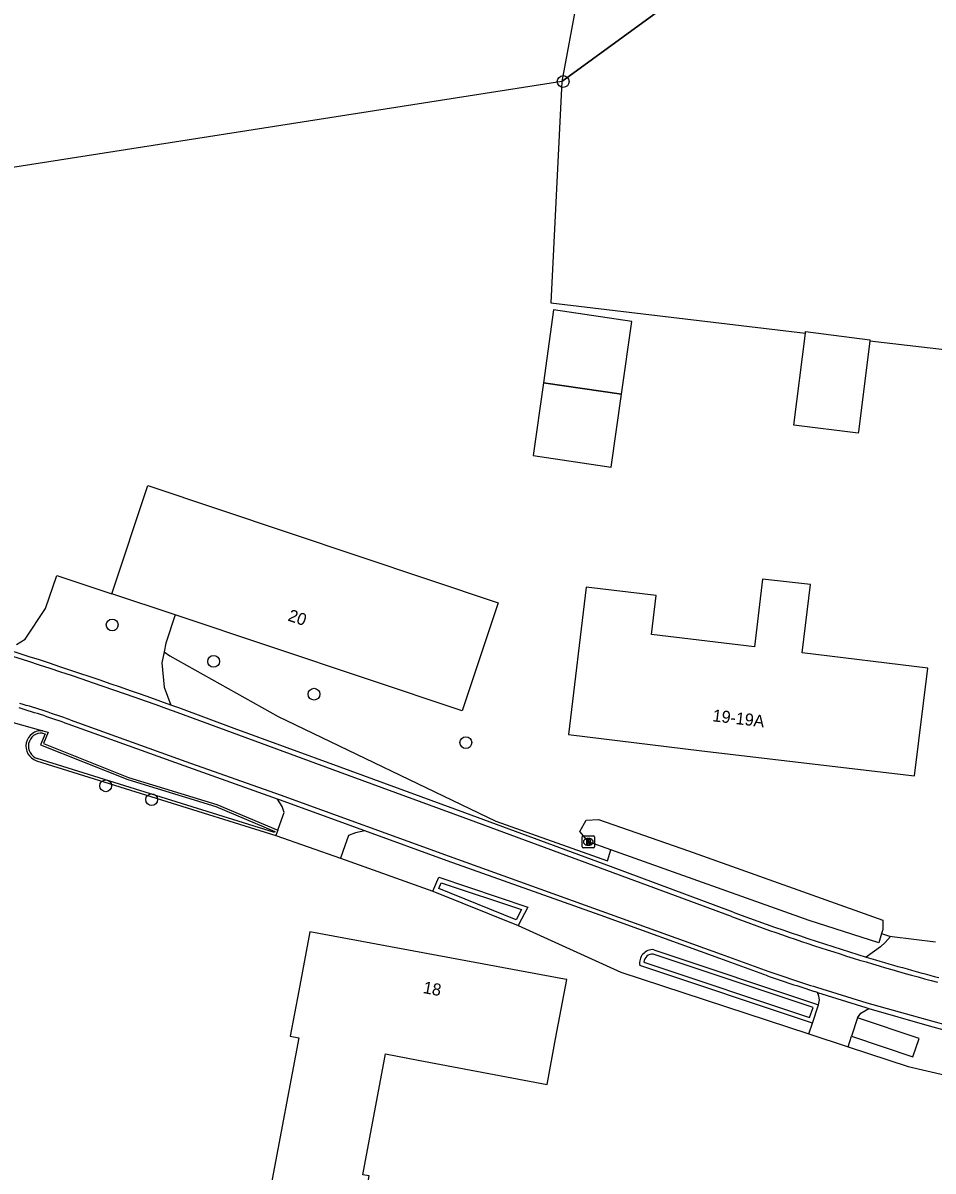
# Model space of a CAD drawing. Extents: x 162515 to 163909, y 388494 to 389773.
# Drawn here: x 162571.4 to 162646.9, y 389047 to 389142.1 of the extents above; entities that cross this region are included whole.
import ezdxf

# ---------------------------------------------------------------- set-up
doc = ezdxf.new("R2010")
doc.units = 0
for name, color, linetype in [('IMGEO_Berm_groen', 7, 'Continuous'), ('IMGEO_Boom', 7, 'Continuous'), ('IMGEO_Erf', 7, 'Continuous'), ('IMGEO_Grasland_agrarisch', 7, 'Continuous'), ('IMGEO_Grasland_overig', 7, 'Continuous'), ('IMGEO_Groenvoorziening', 7, 'Continuous'), ('IMGEO_Hek', 7, 'Continuous'), ('IMGEO_Loofbos', 7, 'Continuous'), ('IMGEO_Pand', 7, 'Continuous'), ('IMGEO_Pand_nummerreeks', 7, 'Continuous'), ('IMGEO_Pand_overbouw', 7, 'Continuous'), ('IMGEO_Rijbaan_lokaal_gesloten', 7, 'Continuous'), ('IMGEO_Rijbaan_lokaal_halfverhard', 7, 'Continuous'), ('IMGEO_Rijbaan_lokaal_open', 7, 'Continuous'), ('IMGEO_Rioolput', 7, 'Continuous'), ('IMGEO_Voetpad_halfverhard', 7, 'Continuous'), ('IMGEO_Voetpad_open', 7, 'Continuous'), ('IMGEO_Waterloop', 7, 'Continuous')]:
    doc.layers.add(name, color=color, linetype=linetype)

msp = doc.modelspace()

# ---------------------------------------------------------------- linework, layer by layer
at = {"layer": 'IMGEO_Berm_groen'}
for points in [[(162597.772, 389072.896), (162605.424, 389070.178)], [(162605.424, 389070.178), (162605.91, 389071.318), (162613.301, 389068.852), (162612.506, 389067.31)], [(162612.506, 389067.31), (162621.016, 389063.464), (162636.603, 389058.338)], [(162623.752, 389065.315), (162637.408, 389060.743)], [(162636.901, 389059.229), (162622.591, 389064.006)]]:
    msp.add_lwpolyline(points, dxfattribs=at)
msp.add_arc((162623.672, 389064.216), 1.102, 85.85497, 191.00304, dxfattribs=at)
at = {"layer": 'IMGEO_Boom'}
for centre in [(162616.233, 389137.29), (162578.829, 389092.237), (162587.236, 389089.214), (162595.566, 389086.496), (162608.163, 389082.483), (162578.292, 389078.903), (162582.101, 389077.76)]:
    msp.add_circle(centre, 0.489, dxfattribs=at)
at = {"layer": 'IMGEO_Erf'}
for points in [[(162572.538, 389080.978), (162592.401, 389074.784)], [(162605.424, 389070.178), (162612.506, 389067.31)]]:
    msp.add_lwpolyline(points, dxfattribs=at)
msp.add_arc((162572.96, 389082.191), 1.284, 84.97508, 250.8354, dxfattribs=at)
at = {"layer": 'IMGEO_Grasland_agrarisch'}
msp.add_lwpolyline([(162616.111, 389137.29), (162556.609, 389127.989)], dxfattribs=at)
at = {"layer": 'IMGEO_Grasland_overig'}
msp.add_lwpolyline([(162633.62, 389150.066), (162631.291, 389155.256), (162618.597, 389150.697), (162616.111, 389137.29)], dxfattribs=at)
at = {"layer": 'IMGEO_Groenvoorziening'}
for points in [[(162583.138, 389090.012), (162583.595, 389089.671), (162592.606, 389084.643), (162610.637, 389075.969), (162619.919, 389072.683), (162620.188, 389073.585)], [(162557.784, 389085.129), (162560.951, 389085.473), (162565.003, 389085.162), (162565.92, 389085.075), (162567.934, 389084.89), (162573.072, 389083.47)], [(162573.072, 389083.47), (162573.519, 389083.346), (162573.142, 389082.396), (162580.177, 389079.602), (162587.495, 389077.364), (162592.559, 389075.234)], [(162642.646, 389066.648), (162643.381, 389066.421)], [(162639.858, 389057.267), (162644.844, 389055.627), (162677.463, 389048.046)]]:
    msp.add_lwpolyline(points, dxfattribs=at)
at = {"layer": 'IMGEO_Hek'}
msp.add_lwpolyline([(162616.111, 389137.29), (162633.62, 389150.066)], dxfattribs=at)
at = {"layer": 'IMGEO_Loofbos'}
for points in [[(162633.62, 389150.066), (162616.111, 389137.29)], [(162616.111, 389137.29), (162615.215, 389118.938), (162636.321, 389116.436)], [(162641.662, 389115.802), (162650.943, 389114.702), (162655.896, 389114.06)]]:
    msp.add_lwpolyline(points, dxfattribs=at)
at = {"layer": 'IMGEO_Pand'}
for points in [[(162621.939, 389117.404), (162615.419, 389118.366), (162614.587, 389112.323), (162621.077, 389111.365), (162621.939, 389117.404)], [(162641.662, 389115.802), (162640.716, 389108.261), (162640.699, 389108.128), (162635.361, 389108.798), (162636.321, 389116.436)], [(162636.321, 389116.436), (162636.336, 389116.556), (162641.673, 389115.886), (162641.662, 389115.802)], [(162578.784, 389094.826), (162581.781, 389103.795), (162610.841, 389094.076), (162607.844, 389085.107), (162584.039, 389093.069)], [(162632.766, 389096.037), (162632.094, 389090.417), (162623.545, 389091.44), (162623.932, 389094.677), (162618.144, 389095.37), (162616.682, 389083.157), (162627.737, 389081.795), (162645.378, 389079.737), (162646.476, 389088.646), (162636.045, 389089.931), (162636.741, 389095.589), (162632.766, 389096.037)], [(162584.039, 389093.069), (162578.784, 389094.826)], [(162604.218, 389056.155), (162614.892, 389054.138), (162615.607, 389057.921), (162616.534, 389062.834), (162616.336, 389062.871), (162595.223, 389066.807), (162594.294, 389061.894), (162593.588, 389058.156), (162594.315, 389058.019), (162592.019, 389045.861), (162592.557, 389045.76), (162591.005, 389037.546), (162598.18, 389036.191), (162600.085, 389046.274), (162600.138, 389046.554), (162599.608, 389046.654), (162601.5, 389056.669), (162604.218, 389056.155)]]:
    msp.add_lwpolyline(points, dxfattribs=at)
at = {"layer": 'IMGEO_Pand_overbouw'}
msp.add_lwpolyline([(162621.077, 389111.365), (162614.587, 389112.323), (162613.755, 389106.274), (162620.212, 389105.312)], close=True, dxfattribs=at)
at = {"layer": 'IMGEO_Rijbaan_lokaal_gesloten'}
for points in [[(162575.34, 389084.366), (162584.931, 389080.923), (162592.748, 389078.167), (162606.773, 389073.076), (162619.448, 389068.517), (162629.327, 389064.949), (162633.3, 389063.513)], [(162630.186, 389068.059), (162619.847, 389071.883), (162607.927, 389076.278), (162597.591, 389080.066), (162588.792, 389083.287), (162584.227, 389084.98)], [(162637.231, 389062.201), (162641.418, 389060.909), (162646.781, 389059.42)]]:
    msp.add_lwpolyline(points, dxfattribs=at)
for centre, radius, start, end in [((162449.728, 388712.327), 396.182, 70.1543, 72.30597), ((162553.555, 389024.708), 63.511, 69.93984, 73.89327), ((162694.778, 389241.263), 184.855, 249.54836, 255.11406), ((162695.7, 389243.931), 190.905, 250.92129, 252.16509), ((162697.827, 389234.609), 182.474, 253.75498, 259.99234)]:
    msp.add_arc(centre, radius, start, end, dxfattribs=at)
at = {"layer": 'IMGEO_Rijbaan_lokaal_halfverhard'}
for points in [[(162630.325, 389068.434), (162620.144, 389072.2), (162608.065, 389076.654), (162597.729, 389080.442), (162588.931, 389083.662), (162584.363, 389085.356), (162583.689, 389085.599)], [(162592.545, 389077.801), (162584.785, 389080.564), (162575.172, 389084.009)], [(162599.769, 389075.181), (162592.692, 389077.749), (162592.545, 389077.801)], [(162633.167, 389063.141), (162629.224, 389064.578), (162619.309, 389068.164), (162606.622, 389072.695), (162599.769, 389075.181)], [(162637.328, 389061.772), (162637.079, 389061.849)], [(162637.328, 389061.772), (162641.34, 389060.522), (162641.596, 389060.449)], [(162641.596, 389060.449), (162646.599, 389059.011)]]:
    msp.add_lwpolyline(points, dxfattribs=at)
for centre, radius, start, end in [((162553.636, 389025.702), 62.157, 69.72791, 73.68109), ((162694.824, 389241.388), 184.589, 249.54808, 253.16879), ((162695.81, 389244.987), 188.32, 253.19886, 255.10164), ((163018.716, 390223.963), 1223.174, 251.626885, 251.819865), ((162705.983, 389271.927), 221.042, 254.41588, 259.58886)]:
    msp.add_arc(centre, radius, start, end, dxfattribs=at)
at = {"layer": 'IMGEO_Rijbaan_lokaal_open'}
for points in [[(162570.879, 389090.626), (162571.596, 389091.063), (162573.303, 389093.589), (162574.241, 389096.331), (162578.784, 389094.826)], [(162584.039, 389093.069), (162583.288, 389090.735), (162583.138, 389090.012)], [(162583.138, 389090.012), (162582.949, 389089.105), (162583.143, 389087.072), (162583.689, 389085.599)]]:
    msp.add_lwpolyline(points, dxfattribs=at)
msp.add_arc((162450.179, 388713.593), 395.238, 70.25732, 72.31315, dxfattribs=at)
at = {"layer": 'IMGEO_Rioolput'}
for p, q in [((162617.818, 389073.829), (162617.818, 389074.681)), ((162617.893, 389074.755), (162618.745, 389074.755)), ((162618.819, 389074.681), (162618.819, 389073.829)), ((162618.745, 389073.755), (162617.893, 389073.755)), ((162618.329, 389073.975), (162618.304, 389073.975)), ((162618.306, 389074.535), (162618.331, 389074.535))]:
    msp.add_line(p, q, dxfattribs=at)
for points in [[(162617.818, 389073.829), (162617.818, 389074.681)], [(162617.893, 389074.755), (162618.745, 389074.755)], [(162618.819, 389074.681), (162618.819, 389073.829)], [(162618.745, 389073.755), (162617.893, 389073.755)], [(162618.407, 389074.453), (162618.155, 389074.455), (162618.155, 389074.055)], [(162618.155, 389074.055), (162618.279, 389074.055), (162618.279, 389074.217), (162618.29, 389074.217)], [(162618.333, 389074.374), (162618.279, 389074.374), (162618.279, 389074.293)], [(162618.279, 389074.293), (162618.331, 389074.293)], [(162618.337, 389074.188), (162618.408, 389074.055), (162618.548, 389074.055), (162618.483, 389074.181)]]:
    msp.add_lwpolyline(points, dxfattribs=at)
for centre, radius, start, end in [((162617.895, 389074.679), 0.0765, 91.55205, 178.44795), ((162617.895, 389074.679), 0.0765, 91.55205, 178.44795), ((162618.743, 389074.679), 0.0765, 1.55205, 88.44795), ((162618.743, 389074.679), 0.0765, 1.55205, 88.44795), ((162617.895, 389073.831), 0.0765, 181.55205, 268.44795), ((162617.895, 389073.831), 0.0765, 181.55205, 268.44795), ((162618.289, 389074.164), 0.0533, 26.02933, 88.69889), ((162618.315, 389074.482), 0.19, 274.7715, 282.96867), ((162618.339, 389074.278), 0.0964, 77.00612, 93.18647), ((162618.353, 389074.335), 0.0378, 276.66336, 79.67722), ((162618.406, 389074.343), 0.109, 350.36119, 89.41601), ((162618.404, 389074.343), 0.112, 277.58423, 350.98172), ((162618.388, 389074.128), 0.108, 29.51342, 73.79051), ((162618.743, 389073.831), 0.0765, 271.55205, 358.44795), ((162618.743, 389073.831), 0.0765, 271.55205, 358.44795)]:
    msp.add_arc(centre, radius, start, end, dxfattribs=at)
for centre, major_axis, ratio, start_param, end_param in [((162618.305, 389074.255), (-0.387, 0.002), 0.722429, 4.712389, 7.853982), ((162618.33, 389074.255), (-0.39, 0.002), 0.717154, 1.570796, 4.712389)]:
    msp.add_ellipse(centre, major_axis=major_axis, ratio=ratio, start_param=start_param, end_param=end_param, dxfattribs=at)
at = {"layer": 'IMGEO_Voetpad_halfverhard'}
for points in [[(162592.559, 389075.234), (162592.998, 389076.477), (162593.077, 389076.701), (162592.93, 389077.198), (162592.545, 389077.801)], [(162592.559, 389075.234), (162592.401, 389074.784)], [(162592.401, 389074.784), (162597.772, 389072.896)], [(162599.769, 389075.181), (162599.005, 389075.013), (162598.439, 389074.769), (162598.136, 389073.919), (162597.772, 389072.896)]]:
    msp.add_lwpolyline(points, dxfattribs=at)
at = {"layer": 'IMGEO_Voetpad_open'}
for points in [[(162643.381, 389066.421), (162642.952, 389065.907), (162642.557, 389065.555), (162641.376, 389064.706)], [(162647.102, 389065.938), (162643.518, 389066.379), (162643.381, 389066.421)], [(162637.408, 389060.743), (162637.478, 389061.162), (162637.435, 389061.466), (162637.328, 389061.772)], [(162636.901, 389059.229), (162637.408, 389060.743)], [(162640.657, 389059.656), (162640.933, 389060.049), (162641.251, 389060.258), (162641.596, 389060.449)], [(162640.657, 389059.656), (162640.151, 389058.145)], [(162636.603, 389058.338), (162636.901, 389059.229)], [(162636.603, 389058.338), (162639.858, 389057.267)], [(162639.858, 389057.267), (162640.151, 389058.145)]]:
    msp.add_lwpolyline(points, dxfattribs=at)
at = {"layer": 'IMGEO_Waterloop'}
for points in [[(162573.045, 389083.274), (162573.256, 389083.215), (162572.887, 389082.286), (162580.112, 389079.417), (162587.428, 389077.179), (162592.313, 389075.125), (162592.279, 389075.028), (162572.607, 389081.162)], [(162620.188, 389073.585), (162618.326, 389074.249), (162617.612, 389075.122), (162618.128, 389076.056), (162619.16, 389076.114), (162626.637, 389073.516), (162642.734, 389067.769), (162642.75, 389066.991), (162642.646, 389066.648)], [(162642.646, 389066.648), (162642.417, 389065.896), (162636.638, 389067.722), (162620.188, 389073.585)], [(162606.12, 389070.852), (162612.766, 389068.634), (162612.329, 389067.787), (162605.92, 389070.383), (162606.12, 389070.852)], [(162622.934, 389064.269), (162636.675, 389059.682), (162636.955, 389060.518), (162623.696, 389064.957)], [(162640.151, 389058.145), (162645.246, 389056.444), (162645.77, 389057.944), (162640.657, 389059.656)]]:
    msp.add_lwpolyline(points, dxfattribs=at)
for centre, radius, start, end in [((162572.96, 389082.19), 1.087, 85.49441, 251.07303), ((162623.668, 389064.222), 0.735, 87.80627, 176.35068)]:
    msp.add_arc(centre, radius, start, end, dxfattribs=at)

# ---------------------------------------------------------------- texts
at = {"layer": 'IMGEO_Pand_nummerreeks'}
for s, rotation, p in [('20', 341.50769, (162593.332, 389092.617)), ('19-19A', 353.14996, (162628.582, 389084.257)), ('18', 349.44039, (162604.557, 389061.731))]:
    msp.add_text(s, height=1, rotation=rotation, dxfattribs=at).set_placement(p)

doc.saveas('drawing.dxf')
